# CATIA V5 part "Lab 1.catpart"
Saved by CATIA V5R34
Part number: Part1
Bounding box of the stored display mesh (mm): x -65 to 65, y -45 to 45, z 0 to 30
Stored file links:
  D:\Artur\Systemy CAM\2025-2026\Dzienne\Machanika i budowa maszyn\Lab 1.catpart
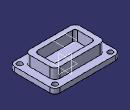
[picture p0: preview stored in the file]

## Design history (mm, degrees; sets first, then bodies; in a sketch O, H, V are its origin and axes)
Set1 "Polfabrykat"
  Sketch1 on {plane stored without definition}, origin (0, 0, -10), H (1, 0, 0), V (0, 1, 0)
    line L1 (-70, -50) -> (70, -50)
    line L2 (70, -50) -> (70, 50)
    line L3 (70, 50) -> (-70, 50)
    line L4 (-70, 50) -> (-70, -50)
  Join1: Elements ({fill Boundary Sketch1}; {fill Boundary {translate ToTransfor Sketch1, Distance 43}}; {loft Sections (Sketch1; {translate ToTransfor Sketch1, Distance 43})})
  Sketch2 on face of Join1, origin (0, 0, 33), H (1, 0, 0), V (0, 1, 0)
    point P1 (-7.0599, 15.8377)
    point P2 (0, 0)
    coincidence: P2 O
Body1 "Kostka" (main body)
  Sketch3 on xy-plane, origin (0, 0, 0), H (1, 0, 0), V (0, 1, 0)
    line L1 (65, 45) -> (65, -45)
    line L2 (65, -45) -> (-65, -45)
    line L3 (-65, -45) -> (-65, 45)
    line L4 (-65, 45) -> (65, 45)
    line L5 (50, 30) -> (50, -30)
    line L6 (50, -30) -> (-50, -30)
    line L7 (-50, -30) -> (-50, 30)
    line L8 (-50, 30) -> (50, 30)
    line L9 (40, 20) -> (40, -20)
    line L10 (40, -20) -> (-40, -20)
    line L11 (-40, -20) -> (-40, 20)
    line L12 (-40, 20) -> (40, 20)
    distance L2 L4 = 90
    distance L1 L3 = 130
    distance L8 L6 = 60
    distance L5 L7 = 100
    distance L12 L10 = 40
    distance L9 L11 = 80
    vertical: L1 V, L3 V, L5 V, L7 V, L9 V, L11 V
    horizontal: L2 H, L4 H, L6 H, L8 H, L10 H, L12 H
    equidistance: L1 L3 O, L2 L4 O, L5 L7 O, L6 L8 O, L9 L11 O, L10 L12 O
  MultiPad1: profile Sketch3, domains (length 10; length 30; length 10)
  Fillet1: radius 10, on edge [face of MultiPad1 from Sketch3.L1 | face of MultiPad1 from Sketch3.L2]; edge [face of MultiPad1 from Sketch3.L5 | face of MultiPad1 from Sketch3.L6]; edge [face of MultiPad1 from Sketch3.L4 | face of MultiPad1 from Sketch3.L1]; edge [face of MultiPad1 from Sketch3.L8 | face of MultiPad1 from Sketch3.L5]; edge [face of MultiPad1 from Sketch3.L2 | face of MultiPad1 from Sketch3.L3]; edge [face of MultiPad1 from Sketch3.L6 | face of MultiPad1 from Sketch3.L7]; edge [face of MultiPad1 from Sketch3.L7 | face of MultiPad1 from Sketch3.L8]; edge [face of MultiPad1 from Sketch3.L3 | face of MultiPad1 from Sketch3.L4]
  Fillet2: radius 5, on edge [face of MultiPad1 from Sketch3.L11 | face of MultiPad1 from Sketch3.L10]; edge [face of MultiPad1 from Sketch3.L9 | face of MultiPad1 from Sketch3.L12]; edge [face of MultiPad1 from Sketch3.L10 | face of MultiPad1 from Sketch3.L9]; edge [face of MultiPad1 from Sketch3.L12 | face of MultiPad1 from Sketch3.L11]
  Sketch4 on face of MultiPad1, origin (-42.0822, 38.8603, 10), H (1, 0, 0), V (0, 1, 0)
    point P1 (-12.9178, -3.8603)
    reference intersected line E1 through (42.0822, 0) direction (0, 1) from yz-plane
    reference intersected line E2 through (0, -38.8603) direction (-1, 0) from zx-plane
    distance P1 E1 = 55
    distance E2 P1 = 35
  Hole1: placed by Sketch4, at (-55, 35, 10) direction (0, 0, -1), diameter 10, through (limit type 6)
  RectPattern1: of Hole1, direction 1 instances 2, spacing 110, along edge [face of MultiPad1 from Sketch3.L4 | face of MultiPad1] reversed, direction 2 instances 2, spacing 70, along edge [face of MultiPad1 from Sketch3.L3 | face of MultiPad1]
  Plane1: type Offset, RefPlane face of MultiPad1, Offset 10, reversed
